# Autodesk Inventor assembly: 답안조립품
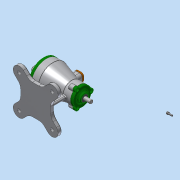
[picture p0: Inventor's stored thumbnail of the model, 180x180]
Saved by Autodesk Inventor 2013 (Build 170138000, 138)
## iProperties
Created: 2018-03
Part Number: 답안조립품
Document SubType Name: Assembly
Designer: Administrator
Author: Administrator
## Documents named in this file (15)
- C:\Users\Administrator\Desktop\480308V1016\답안조립품.iam
- C:\Users\Administrator\Desktop\480308V1016\뒤커버.ipt
- C:\Users\Administrator\Desktop\480308V1016\마개.ipt
- C:\Users\Administrator\Desktop\480308V1016\베어링-6200.ipt
- C:\Users\Administrator\Desktop\480308V1016\베어링-6203.ipt
- C:\Users\Administrator\Desktop\480308V1016\본체.ipt
- C:\Users\Administrator\Desktop\480308V1016\볼트 M4 x 12.ipt
- 볼트 M4 x 12.ipt
- C:\Users\Administrator\Desktop\480308V1016\스프로킷.ipt
- C:\Users\Administrator\Desktop\480308V1016\앞커버.ipt
- C:\Users\Administrator\Desktop\480308V1016\오일 실 10 20 7.ipt
- C:\Users\Administrator\Desktop\480308V1016\오일 실 17 30 8.ipt
- C:\Users\Administrator\Desktop\480308V1016\축.ipt
- C:\Users\Administrator\Desktop\480308V1016\키 5 x 5.ipt
- 키 5 x 5.ipt
